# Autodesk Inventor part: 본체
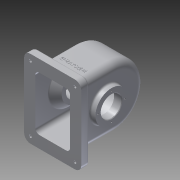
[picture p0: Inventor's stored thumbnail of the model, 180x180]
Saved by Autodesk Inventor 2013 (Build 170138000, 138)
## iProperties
Created: 2016-10
Part Number: 본체
Material: 알루미늄 6061
Document SubType Name: Modeling
Designer: Administrator
Density: 2.71 g/cm^3
Mass: 1165.23 g
Surface Area: 1199.61 cm^2
Volume: 429.976 cm^3
Author: Administrator
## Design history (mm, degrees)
sketch "스케치1"
  geometry: L1 (0, -58)-(-80, -58); L2 (-80, -58)-(-80, 58); L3 (-80, 58)-(0, 58); L4 (0, 58)-(0, -58); L5 (0, -58)-(58, -58); L6 (58, -58)-(58, 58); L7 (58, 58)-(0, 58); L8 (0, 58)-(0, -58); 2 further points
  constraints: 16 end point, 4 parallel, 2 horizontal, 2 perpendicular, 1 coincident, 1 midpoint
  dimensions: "d0" = 116 distance of L3.end L1.start; "d2" = 80 distance of L2.end L3.end; "d3" = 116 distance of L5.end L6.end; "d4" = 58 distance of L6.end L7.end
extrude "돌출1" new body sketch "스케치1" stored distance "d5" = 77; taper "d6" = 0 deg
fillet "모깎기1" dims "d7" = 58
sketch "스케치2"
  geometry: L1 (-38.5, -80)-(-38.5, 58) reference; L2 (-38.5, 58)-(38.5, 58) reference; L3 (38.5, 58)-(38.5, -80) reference; L4 (38.5, -80)-(-38.5, -80) reference; L5 (-33.5, 52)-(33.5, 52); L6 (33.5, 52)-(33.5, 0); L7 (33.5, 0)-(-33.5, 0); L8 (-33.5, 0)-(-33.5, 52); 2 further points
  constraints: 8 end point, 2 parallel, 1 coincident, 1 horizontal, 1 midpoint, 1 perpendicular
  dimensions: "d8" = 5 distance between parallel lines of L1 L8; "d9" = 52 distance between parallel lines of L7 L5
revolve "회전1" sketch "스케치2" stored, may be unused: angle "d10" = 90 deg
sketch "스케치3"
  geometry: L1 (-38.5, -80)-(-38.5, 58) reference; L2 (-38.5, 58)-(38.5, 58) reference; L3 (38.5, 58)-(38.5, -80) reference; L4 (38.5, -80)-(-38.5, -80) reference; L5 (33.5, -52)-(33.5, 52) reference; L6 (33.5, 52)-(-33.5, 52) reference; L7 (-33.5, 52)-(-33.5, -52) reference; L8 (-33.5, -52)-(33.5, -52) reference; L9 (-33.5, 0)-(33.5, 0); L10 (33.5, 0)-(33.5, -80); L11 (33.5, -80)-(-33.5, -80); L12 (-33.5, -80)-(-33.5, 0); 1 further point
  constraints: 8 end point, 2 parallel, 1 horizontal, 1 midpoint, 1 perpendicular, 1 point on line
  dimensions: "d11" = 5 distance between parallel lines of L3 L10
extrude "돌출2" cut sketch "스케치3" stored distance "d12" = 104; taper "d13" = 0 deg
sketch "스케치4"
  geometry: L1 (72, 6)-(5, 6) reference; L2 (5, 6)-(5, 110) reference; L3 (5, 110)-(72, 110) reference; L4 (72, 110)-(72, 6) reference; L5 (93.5, 133)-(-16.5, 133); L6 (-16.5, 133)-(-16.5, -17); L7 (-16.5, -17)-(93.5, -17); L8 (93.5, -17)-(93.5, 133); L9 (93.5, 133)-(-16.5, -17); L10 (-16.5, 133)-(93.5, -17); 1 further point
  constraints: 12 end point, 2 midpoint, 2 parallel, 1 horizontal, 1 perpendicular
  dimensions: "d14" = 110 distance of L6.end L7.end; "d16" = 150 distance of L7.end L5.start
extrude "돌출3" join sketch "스케치4" distance "d17" = 15; taper "d18" = 0 deg
sketch "스케치5"
  geometry: L1 (-33.5, 52)-(-33.5, -80) reference; L2 (-33.5, -80)-(-55, -80) reference; L3 (-55, -80)-(-55, -65) reference; L4 (-55, -65)-(-38.5, -65) reference; L5 (-38.5, -65)-(-38.5, 58) reference; L6 (-38.5, 58)-(38.5, 58) reference; L7 (38.5, 58)-(38.5, -65) reference; L8 (38.5, -65)-(55, -65) reference; L9 (55, -65)-(55, -80) reference; L10 (55, -80)-(33.5, -80) reference; L11 (33.5, -80)-(33.5, 52) reference; L12 (33.5, 52)-(-33.5, 52) reference; L13 (37.5, -15)-(48.5, -15); L14 (48.5, -15)-(48.5, 16); L15 (48.5, 16)-(37.5, 16); L16 (37.5, 16)-(37.5, -15); L17 (33.5, -15)-(38.5, -15); 1 further point
  constraints: 10 end point, 3 point on line, 2 parallel, 2 perpendicular, 1 horizontal
  dimensions: "d20" = 87 distance between parallel lines of L5 L14; "d21" = 31 distance of L13.end L14.end; "d22" = 11 distance of L14.end L15.end; "d23" = 65 distance between parallel lines of L10 L13
revolve "회전2" sketch "스케치5" stored, may be unused: angle "d24" = 90 deg
sketch "스케치6"
  geometry: L1 (-33.5, 52)-(-33.5, -80) reference; L2 (-33.5, -80)-(-55, -80) reference; L3 (-55, -80)-(-55, -65) reference; L4 (-55, -65)-(-38.5, -65) reference; L5 (-38.5, -65)-(-38.5, 58) reference; L6 (-38.5, 58)-(38.5, 58) reference; L7 (38.5, 58)-(38.5, 16) reference; L8 (38.5, 16)-(48.5, 16) reference; L9 (48.5, 16)-(48.5, -46) reference; L10 (48.5, -46)-(38.5, -46) reference; L11 (38.5, -46)-(38.5, -65) reference; L12 (38.5, -65)-(55, -65) reference; L13 (55, -65)-(55, -80) reference; L14 (55, -80)-(33.5, -80) reference; L15 (33.5, -80)-(33.5, 52) reference; L16 (33.5, 52)-(-33.5, 52) reference; L17 (-43.5, 22.5)-(-36.5, 22.5); L18 (-36.5, 22.5)-(-36.5, -15); L19 (-36.5, -15)-(-43.5, -15); L20 (-43.5, -15)-(-43.5, 22.5); 1 further point
  constraints: 8 end point, 2 parallel, 1 horizontal, 1 perpendicular
  dimensions: "d25" = 65 distance between parallel lines of L2 L19; "d26" = 37.5 distance of L19.end L17.start; "d27" = 5 distance between parallel lines of L5 L20; "d28" = 7 distance of L17.start L17.end
revolve "회전3" sketch "스케치6" stored, may be unused: angle "d29" = 90 deg
sketch "스케치7"
  geometry: L1 (-33.5, 52)-(-33.5, -80) reference; L2 (-33.5, -80)-(-55, -80) reference; L3 (-55, -80)-(-55, -65) reference; L4 (-55, -65)-(-38.5, -65) reference; L5 (-38.5, -65)-(-38.5, -52.5) reference; L6 (-38.5, -52.5)-(-43.5, -52.5) reference; L7 (-43.5, -52.5)-(-43.5, 22.5) reference; L8 (-43.5, 22.5)-(-38.5, 22.5) reference; L9 (-38.5, 22.5)-(-38.5, 58) reference; L10 (-38.5, 58)-(38.5, 58) reference; L11 (38.5, 58)-(38.5, 16) reference; L12 (38.5, 16)-(48.5, 16) reference; L13 (48.5, 16)-(48.5, -46) reference; L14 (48.5, -46)-(38.5, -46) reference; L15 (38.5, -46)-(38.5, -65) reference; L16 (38.5, -65)-(55, -65) reference; L17 (55, -65)-(55, -80) reference; L18 (55, -80)-(33.5, -80) reference; L19 (33.5, -80)-(33.5, 52) reference; L20 (33.5, 52)-(-33.5, 52) reference; L21 (-43.5, -15)-(48.5, -15); L22 (-33.5, 13)-(-19.5, 13); L23 (-19.5, 13)-(-19.5, -15); L24 (-19.5, 13)-(-33.5, 24.747); L25 (-33.5, 24.747)-(-33.5, -15); L26 (-33.5, -15)-(-19.5, -15); 1 further point
  constraints: 12 end point, 5 point on line, 2 midpoint, 2 parallel
  dimensions: "d31" = 65 distance between parallel lines of L2 L21; "d32" = 28 distance between parallel lines of L21 L22; "d34" = 50 deg angle of L23 L24; "d35" = 24 distance between parallel lines of L7 L23
revolve "회전4" sketch "스케치7" stored, may be unused: angle "d36" = 90 deg
sketch "스케치8"
  geometry: C1 r 31 at (0, 0) reference; C2 r 20 at (0, 0); 1 further point
  constraints: 1 centre point, 1 coincident
  dimensions: "d37" = 40 diameter of C2
extrude "돌출4" cut sketch "스케치8" stored distance "d38" = 15; taper "d39" = 0 deg
chamfer "모따기1" distance "d40" = 1; stored, may be unused: second distance "d41" = 2, angle "d42" = 45 deg
sketch "스케치9"
  geometry: L1 (48.5, 6)-(47.5, 5) reference; L2 (47.5, 5)-(33.5, 5) reference; L3 (33.5, 5)-(33.5, 52) reference; L4 (33.5, 52)-(-33.5, 52) reference; L5 (-33.5, 52)-(-33.5, 24.747) reference; L6 (-33.5, 24.747)-(-19.5, 13) reference; L7 (-19.5, 13)-(-19.5, 5) reference; L8 (-19.5, 5)-(-42.5, 5) reference; L9 (-42.5, 5)-(-43.5, 6) reference; L10 (-43.5, 6)-(-43.5, 22.5) reference; L11 (-43.5, 22.5)-(-38.5, 22.5) reference; L12 (-38.5, 22.5)-(-38.5, 58) reference; L13 (-38.5, 58)-(38.5, 58) reference; L14 (38.5, 58)-(38.5, 16) reference; L15 (38.5, 16)-(48.5, 16) reference; L16 (48.5, 16)-(48.5, 6) reference; L17 (-55, -65)-(-38.5, -65) reference; L18 (-38.5, -65)-(-38.5, -52.5) reference; L19 (-38.5, -52.5)-(-43.5, -52.5) reference; L20 (-43.5, -52.5)-(-43.5, -36) reference; L21 (-43.5, -36)-(-42.5, -35) reference; L22 (-42.5, -35)-(-19.5, -35) reference; L23 (-19.5, -35)-(-19.5, -43) reference; L24 (-19.5, -43)-(-33.5, -54.747) reference; L25 (-33.5, -54.747)-(-33.5, -80) reference; L26 (-33.5, -80)-(-55, -80) reference; L27 (-55, -80)-(-55, -65) reference; L28 (38.5, -65)-(55, -65) reference; L29 (55, -65)-(55, -80) reference; L30 (55, -80)-(33.5, -80) reference; L31 (33.5, -80)-(33.5, -35) reference; L32 (33.5, -35)-(47.5, -35) reference; L33 (47.5, -35)-(48.5, -36) reference; L34 (48.5, -36)-(48.5, -46) reference; L35 (48.5, -46)-(38.5, -46) reference; L36 (38.5, -46)-(38.5, -65) reference; L37 (-6, 64)-(0, 64); L38 (0, 64)-(0, 55); L39 (-6, 55)-(-6, 64); L40 (-7.587, 55)-(0, 55); L41 (-6, 64)-(-7.587, 55); 1 further point
  constraints: 10 end point, 2 perpendicular, 1 horizontal, 1 parallel, 1 point on line
  dimensions: "d43" = 33.5 distance between parallel lines of L5 L38; "d44" = 144 distance between parallel lines of L26 L37; "d45" = 6 distance of L37.start L37.end; "d46" = 100 deg angle of L13 L41; "d47" = 9 distance between parallel lines of L37 L40
revolve "회전5" sketch "스케치9" stored, may be unused: angle "d48" = 90 deg
sketch "스케치10" dims "d49" = 58
  geometry: C1 r 21 at (0, 0) reference; 3 further points
  constraints: 1 coincident, 1 vertical alignment, 2 other
  dimensions: "d72" = 14 distance of point (0, 15) point (0, 29)
hole "구멍1" sketch "스케치10" at (0, 29) diameter "d50" = 2.459; stored, may be unused: countersink angle "d54" = 90 deg, drill point angle "d56" = 118 deg; dims "d51" = 6, "d52" = 4, "d53" = 2, "d55" = 8
sketch "스케치11" dims "d60" = 52
  geometry: C1 r 21 at (0, 0) reference; 3 further points
  constraints: 1 coincident, 1 vertical alignment, 2 other
  dimensions: "d61" = 11 distance of point (0, 15) point (0, 26)
hole "구멍2" sketch "스케치11" at (0, 26) diameter "d62" = 2.459; stored, may be unused: countersink angle "d66" = 90 deg, drill point angle "d68" = 118 deg; dims "d63" = 6, "d64" = 4, "d65" = 2, "d67" = 8
fillet "모깎기2" dims "d73" = 13
fillet "모깎기3" dims "d74" = 8
fillet "모깎기4" dims "d75" = 12
sketch "스케치12"
  geometry: C1 r 6 at (0, 0) reference; 1 further point
  constraints: 1 coincident
hole "구멍3" sketch "스케치12" at (0, 0) diameter "d76" = 4.459; stored, may be unused: countersink angle "d80" = 90 deg, drill point angle "d82" = 118 deg; dims "d77" = 6, "d78" = 4, "d79" = 2, "d81" = 15
sketch "스케치13"
  geometry: C1 r 6 at (-4.5, 5); C2 r 6 at (81.5, 5); C3 r 6 at (81.5, -121); C4 r 6 at (-4.5, -121); A1 r 12 centre (81.5, 5) between (93.5, 5) and (81.5, 17) reference; A2 r 12 centre (-4.5, 5) between (-4.5, 17) and (-16.5, 5) reference; A3 r 12 centre (-4.5, -121) between (-16.5, -121) and (-4.5, -133) reference; A4 r 12 centre (81.5, -121) between (81.5, -133) and (93.5, -121) reference; 1 further point
  constraints: 4 centre point, 4 coincident
  dimensions: "d83" = 12 diameter of C1; "d84" = 12 diameter of C2; "d85" = 12 diameter of C3; "d86" = 12 diameter of C4
extrude "돌출5" cut sketch "스케치13" distance "d87" = 5; taper "d88" = 0 deg
sketch "스케치14"
  geometry: C1 r 2.5 at (-4.5, 5); C2 r 2.5 at (81.5, 5); C3 r 2.5 at (81.5, -121); C4 r 2.5 at (-4.5, -121); A1 r 12 centre (81.5, 5) between (93.5, 5) and (81.5, 17) reference; A2 r 12 centre (-4.5, 5) between (-4.5, 17) and (-16.5, 5) reference; A3 r 12 centre (-4.5, -121) between (-16.5, -121) and (-4.5, -133) reference; A4 r 12 centre (81.5, -121) between (81.5, -133) and (93.5, -121) reference; 1 further point
  constraints: 4 centre point, 4 coincident
  dimensions: "d89" = 5 diameter of C1; "d90" = 5 diameter of C2; "d91" = 5 diameter of C3; "d92" = 5 diameter of C4
extrude "돌출6" cut sketch "스케치14" stored distance "d93" = 5; taper "d94" = 0 deg
fillet "모깎기5" dims "d95" = 3
fillet "모깎기6" dims "d96" = 3
fillet "모깎기7" dims "d97" = 3
fillet "모깎기8" dims "d98" = 3
sketch "스케치15"
  geometry: L1 (-17.5, -80)-(-29.5, -80) reference; L2 (-13, 0)-(-13, -62) reference; 2 further points
  constraints: 1 other
  dimensions: "d99" = 40 distance from line of L1 point (25.5, -40); "d100" = 38.5 distance from line of point (25.5, -40) L2
feature "엠보싱1" sketch "스케치15" dims "d0" = 116, "d2" = 80, "d3" = 116, "d4" = 58, "d101" = 0.5, "d102" = 0
node "솔리드1"
pattern_circular "원형 패턴1" dims angle "d58" = 360 deg
pattern_circular "원형 패턴2" dims angle "d70" = 360 deg
node "절단 모서리 투영1"
node "절단 모서리 투영2"
node "절단 모서리 투영3"
node "절단 모서리 투영4"
node "절단 모서리 투영5"
node "절단 모서리 투영6"
other parameters: "d19" = 65
